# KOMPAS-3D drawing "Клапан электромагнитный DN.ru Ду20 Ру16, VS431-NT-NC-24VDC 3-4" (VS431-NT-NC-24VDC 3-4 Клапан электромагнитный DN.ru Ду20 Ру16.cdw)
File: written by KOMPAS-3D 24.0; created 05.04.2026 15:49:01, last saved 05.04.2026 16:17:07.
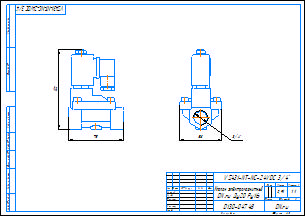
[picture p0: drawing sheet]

Document properties: c3d_UniqueCompID: ef56311e-7521-43dc-8291-0e6108b3d81d; Автор: artio; Класс точности: c; Знак неуказанной шероховатости: Шероховатость не задана; Рассекать на разрезах: Да; Автор: artio; Форматы листов документа: A3; Полное имя файла: VS431-NT-NC-24VDC 3-4 Клапан электромагнитный DN.ru Ду20 Ру16.m3d; Масса: 0.907; Наименование: Клапан электромагнитный DN.ru Ду20 Ру16; Количество листов документа: 1; Примечание: D130-04748

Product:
- Body: Тело 1  | qty 1
    Масса: 1.198355
- Part/product: Клапан электромагнитный DN.ru Ду20 Ру16  | designation VS431-NT-NC-24VDC 3-4
    Масса: 0.907
    Раздел спецификации: Прочие изделия
    Примечание: D130-04748
    additional columns: ef56311e-7521-43dc-8291-0e6108b3d81d; artio; c; Шероховатость не задана; Да

Views: Вид 1, Спереди, Проекционный вид 2
Referenced files in C:\Users\artio\OneDrive\Рабочий стол\Клапан электромагнитный DN.ru\VS431\VS431-ET-NC\: VS431-ET-NC-24VDC 3-4 Клапан электромагнитный DN.ru Ду20 Ру16.m3d
Referenced files in C:\Users\artio\OneDrive\Рабочий стол\Клапан электромагнитный DN.ru\VS431\VS431-NT-NC\: VS431-NT-NC-24VDC 3-4 Клапан электромагнитный DN.ru Ду20 Ру16.m3d, VS431-NT-NC-24VDC 3-4 Клапан электромагнитный DN.ru Ду20 Ру16.cdw
Referenced files in C:\Users\artio\OneDrive\Рабочий стол\Клапан электромагнитный DN.ru\VS431\VS431-NT-NC\VS431-NT-NC-24VDC\Ду20\: VS431-NT-NC-24VDC 3-4 Клапан электромагнитный DN.ru Ду20 Ру16.m3d
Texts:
  VS431-NT-NC-24VDC 3-4
  Клапан электромагнитный
  DN.ru Ду20 Ру16
  VS431-NT-NC-24VDC 3/4"
  VS431-NT-NC-24VDC 3/4"-
  Клапан электромагнитный DN.ru Ду20 Ру16
  VS431-NT-NC-24VDC 3-4 Клапан электромагнитный DN.ru Ду20 Ру16
Dimensions and other numbers on the sheet: 0; 3; 2; 4; 58; 3/4"; 75; 110; 1:1; 1; 0,91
